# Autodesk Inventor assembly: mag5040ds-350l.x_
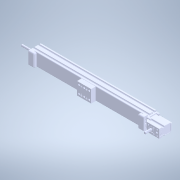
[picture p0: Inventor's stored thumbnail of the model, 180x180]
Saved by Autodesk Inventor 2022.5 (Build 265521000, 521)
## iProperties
Created: 2023-04
Part Number: mag5040ds-350l.x_
Document SubType Name: Assembly
Designer: ImaoCorp
Sending System: SOLIDWORKS 2021-2021301
MC: AMD64
MC_MODEL: Intel64 Family 6 Model 60 Stepping 3, GenuineIntel
OS: Windows_NT
FRU: Parasolid Version 32.1, build 255,  1- 1-2021
FORMAT: text
GUISE: transmit
KEY: mag5040ds-350l
FILE: mag5040ds-350l.x_t
DATE: Wed Apr 12 15:44:14 2023
Author: ImaoCorp
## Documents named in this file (4)
- X:\14_SW2022-Inv2022\00_全2023-1023新製品(TCC)まで\m\mag5040ds-350l\MAG5040DS-350L.iam
- X:\14_SW2022-Inv2022\00_全2023-1023新製品(TCC)まで\m\mag5040ds-350l\mag5040ds-350l_01.ipt
- X:\14_SW2022-Inv2022\00_全2023-1023新製品(TCC)まで\m\mag5040ds-350l\mag5040ds-350l_02.ipt
- X:\14_SW2022-Inv2022\00_全2023-1023新製品(TCC)まで\m\mag5040ds-350l\mag5040ds-350l_03.ipt
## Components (3 placed, 3 different names)
1. mag5040ds-350l_01
2. mag5040ds-350l_02
3. mag5040ds-350l_03
